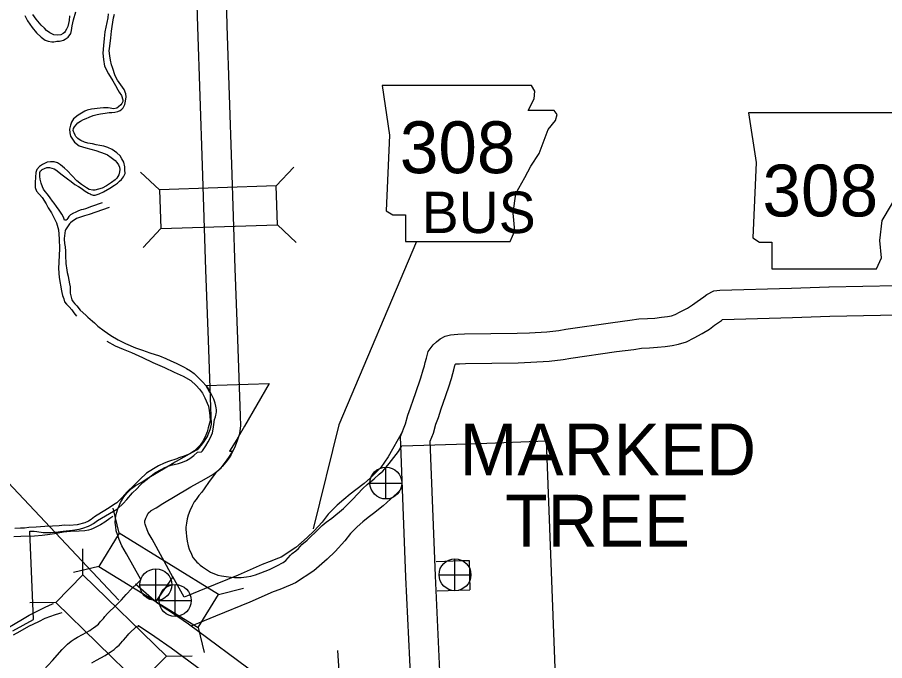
# Model space of a CAD drawing. Extents: x -117616 to 64730, y 54117 to 789866.
# Drawn here: x 61631.6 to 61720, y 55976 to 56041.5 of the extents above; entities that cross this region are included whole.
import ezdxf

# ---------------------------------------------------------------- set-up
doc = ezdxf.new("R2010")
doc.units = 0
for name, color, linetype in [('Level 10', 7, 'Continuous'), ('Level 15', 7, 'Continuous'), ('Level 20', 7, 'Continuous'), ('Level 21', 7, 'Continuous'), ('Level 22', 7, 'Continuous'), ('Level 26', 7, 'Continuous'), ('Level 6', 7, 'Continuous'), ('Level 9', 7, 'Continuous')]:
    doc.layers.add(name, color=color, linetype=linetype)

msp = doc.modelspace()

# ---------------------------------------------------------------- linework, layer by layer
at = {"layer": 'Level 10'}
for p, q in [((61677.652, 55986.174), (61677.742, 55983.175)), ((61647.471, 55984.484), (61645.699, 55981.966))]:
    msp.add_line(p, q, dxfattribs=at)
for points in [[(61647.41, 55996.047), (61647.821, 55996.291), (61649.176, 55997.023), (61649.898, 55997.454), (61650.109, 55997.602), (61650.157, 55997.644), (61650.334, 55997.885), (61650.49, 55998.068), (61650.598, 55998.2), (61650.735, 55998.405), (61650.987, 55998.804), (61651.076, 55999.01), (61651.273, 55999.512), (61651.351, 55999.761), (61651.392, 56000.055), (61651.366, 56000.828), (61651.102, 56008.617), (61650.824, 56015.808), (61650.473, 56026.444), (61650.008, 56040.58), (61649.878, 56045.135)], [(61648.946, 55993.47), (61649.302, 55993.682), (61650.658, 55994.414), (61651.532, 55994.936), (61651.961, 55995.237), (61652.375, 55995.597), (61652.687, 55996.021), (61652.797, 55996.15), (61653.012, 55996.414), (61653.249, 55996.767), (61653.65, 55997.402), (61653.851, 55997.871), (61654.103, 55998.513), (61654.288, 55999.1), (61654.399, 55999.897), (61654.364, 56000.929), (61654.1, 56008.726), (61653.822, 56015.915), (61653.472, 56026.543), (61653.007, 56040.672), (61652.882, 56045.045)], [(61714.345, 56014.067), (61728.08, 56014.327)], [(61671.813, 55971.825), (61671.216, 55984.46), (61670.674, 55998.81), (61671.16, 56000.094), (61671.409, 56000.982), (61671.69, 56001.744), (61671.981, 56002.609), (61672.194, 56003.189), (61672.729, 56004.796), (61672.983, 56005.603), (61673.102, 56006.012), (61673.19, 56006.357), (61673.303, 56006.79), (61673.487, 56007.48), (61673.792, 56007.868), (61674, 56008.141), (61674.345, 56008.469), (61674.694, 56008.748), (61675.206, 56009.046), (61675.756, 56009.177), (61676.505, 56009.221), (61677.188, 56009.262), (61682.545, 56009.323), (61683.798, 56009.387), (61685.572, 56009.484), (61686.785, 56009.61), (61687.509, 56009.758), (61692.291, 56010.443), (61694.043, 56010.66), (61694.937, 56010.784), (61695.846, 56010.834), (61696.589, 56010.885), (61697.266, 56010.962), (61697.862, 56011.042), (61698.28, 56011.123), (61698.654, 56011.236), (61699.175, 56011.507), (61699.894, 56011.894), (61700.432, 56012.229), (61700.892, 56012.584), (61701.579, 56013.049), (61701.861, 56013.275), (61702.595, 56013.653), (61703.19, 56013.725), (61710.506, 56013.931), (61714.32, 56014.067)], [(61674.849, 55971.134), (61674.214, 55984.588), (61673.695, 55998.316), (61674.013, 55999.156), (61674.265, 56000.057), (61674.519, 56000.746), (61674.811, 56001.613), (61675.025, 56002.197), (61675.583, 56003.872), (61675.855, 56004.734), (61675.996, 56005.221), (61676.095, 56005.607), (61676.204, 56006.027), (61676.228, 56006.114), (61676.243, 56006.134), (61676.317, 56006.205), (61676.682, 56006.227), (61677.294, 56006.263), (61682.639, 56006.324), (61683.956, 56006.392), (61685.809, 56006.492), (61687.241, 56006.642), (61688.021, 56006.801), (61692.688, 56007.469), (61694.433, 56007.685), (61695.226, 56007.795), (61696.031, 56007.84), (61696.861, 56007.897), (61697.635, 56007.984), (61698.349, 56008.081), (61699.001, 56008.207), (61699.79, 56008.446), (61700.578, 56008.855), (61701.4, 56009.298), (61702.145, 56009.762), (61702.651, 56010.152), (61703.36, 56010.632), (61703.486, 56010.732), (61710.601, 56010.933), (61714.426, 56011.069)], [(61714.401, 56011.068), (61728.152, 56011.328)], [(61670.881, 55999.307), (61669.403, 55996.717), (61668.658, 55995.642), (61668.215, 55995.19), (61667.589, 55994.603), (61666.959, 55994.018), (61666.104, 55993.354), (61665.52, 55992.917), (61664.876, 55992.391), (61664.196, 55991.794), (61663.279, 55990.883), (61662.684, 55990.077), (61661.877, 55989.201), (61661.158, 55988.518), (61659.999, 55987.498), (61658.496, 55986.512), (61658.239, 55986.395), (61657.294, 55986.013)], [(61644.188, 55984.233), (61642.753, 55986.852), (61642.266, 55987.66), (61641.998, 55988.318), (61641.851, 55988.724), (61641.705, 55989.197), (61641.641, 55989.592), (61641.587, 55990.056), (61641.658, 55990.764), (61641.852, 55991.449), (61641.995, 55991.74), (61642.138, 55992.075), (61642.473, 55992.67), (61642.761, 55993.025), (61643.249, 55993.517), (61643.669, 55993.826), (61644.234, 55994.12), (61644.858, 55994.526), (61647.597, 55996.158)], [(61647.477, 55984.474), (61645.354, 55988.347), (61644.957, 55989.007), (61644.799, 55989.394), (61644.696, 55989.681), (61644.633, 55989.882), (61644.613, 55990.005), (61644.604, 55990.082), (61644.616, 55990.201), (61644.664, 55990.37), (61644.723, 55990.489), (61644.833, 55990.747), (61644.962, 55990.976), (61644.995, 55991.017), (61645.215, 55991.239), (61645.259, 55991.271), (61645.749, 55991.526), (61646.445, 55991.98), (61649.132, 55993.581)], [(61670.795, 55993.536), (61670.314, 55993.045), (61669.635, 55992.409), (61668.903, 55991.73), (61667.923, 55990.968), (61667.367, 55990.553), (61666.816, 55990.102), (61666.245, 55989.601), (61665.556, 55988.916), (61665.001, 55988.164), (61664.016, 55987.095), (61663.182, 55986.304), (61661.822, 55985.106), (61659.947, 55983.876), (61659.422, 55983.637), (61658.365, 55983.21), (61658.261, 55983.172)], [(61657.485, 55986.09), (61657.294, 55986.013), (61656.575, 55985.754), (61654.135, 55984.682), (61650.687, 55983.272), (61648.949, 55982.553), (61648.623, 55982.419), (61647.471, 55984.484)], [(61674.284, 55986.072), (61676.896, 55986.151)], [(61676.897, 55986.151), (61677.652, 55986.174)], [(61658.61, 55983.309), (61658.365, 55983.21), (61657.687, 55982.966), (61655.307, 55981.92), (61651.828, 55980.498), (61650.094, 55979.78), (61649.568, 55979.564), (61649.329, 55979.479)], [(61674.41, 55983.074), (61677.742, 55983.175)]]:
    msp.add_lwpolyline(points, dxfattribs=at)
at = {"layer": 'Level 15'}
for points in [[(61633.884, 55974.536), (61635.186, 55975.957), (61636.182, 55977.102), (61636.741, 55977.626), (61637.116, 55977.95), (61637.4, 55978.142), (61637.748, 55978.344), (61638.257, 55978.622), (61639.002, 55979.032), (61639.179, 55979.154), (61639.394, 55979.311), (61639.624, 55979.459), (61639.739, 55979.566), (61639.882, 55979.687), (61640.065, 55979.9), (61640.199, 55980.051), (61640.391, 55980.261), (61640.537, 55980.442), (61640.809, 55980.752), (61641.686, 55981.614), (61642.219, 55982.17), (61642.714, 55982.707), (61643.282, 55983.311), (61643.826, 55983.836), (61644.188, 55984.188)], [(61667.248, 55966.409), (61659.949, 55971.71), (61656.025, 55974.518), (61649.047, 55979.666), (61647.318, 55980.868), (61646.593, 55981.352), (61646.235, 55981.563), (61645.835, 55981.85), (61643.674, 55983.76)], [(61639.219, 55975.729), (61639.7, 55975.992), (61640.576, 55976.475), (61640.912, 55976.705), (61641.092, 55976.836), (61641.473, 55977.081), (61641.732, 55977.322), (61642.001, 55977.55), (61642.327, 55977.929), (61642.428, 55978.043), (61642.666, 55978.304), (61642.833, 55978.51), (61642.991, 55978.69), (61643.797, 55979.482)], [(61663.181, 55965.668), (61658.196, 55969.275), (61654.261, 55972.092), (61647.3, 55977.227), (61645.629, 55978.388), (61644.996, 55978.811), (61644.595, 55979.048), (61643.963, 55979.5), (61643.946, 55979.516), (61643.853, 55979.421)]]:
    msp.add_lwpolyline(points, dxfattribs=at)
at = {"layer": 'Level 20'}
for p, q in [((61646.113, 56023.953), (61644.186, 56025.757)), ((61657.987, 56024.344), (61659.791, 56026.271)), ((61646.243, 56019.995), (61644.439, 56018.068)), ((61658.117, 56020.386), (61660.044, 56018.582)), ((61641.982, 55988.937), (61641.369, 55991.505)), ((61638.309, 55984.719), (61638.278, 55987.359)), ((61639.908, 55985.563), (61637.34, 55984.951)), ((61652.103, 55982.717), (61654.671, 55983.33)), ((61635.542, 55981.886), (61632.902, 55981.855)), ((61650.029, 55979.343), (61650.642, 55976.775)), ((61646.807, 55976.418), (61649.447, 55976.449)), ((61664.446, 55974.371), (61664.268, 55977.005))]:
    msp.add_line(p, q, dxfattribs=at)
for points in [[(61646.243, 56019.995), (61658.117, 56020.386), (61657.987, 56024.344), (61646.113, 56023.953)], [(61652.103, 55982.717), (61641.982, 55988.937), (61639.908, 55985.563), (61650.029, 55979.343)], [(61646.807, 55976.418), (61638.309, 55984.719), (61635.542, 55981.886), (61644.04, 55973.585)]]:
    msp.add_lwpolyline(points, close=True, dxfattribs=at)
at = {"layer": 'Level 21'}
msp.add_line((61684.02, 56034.585), (61684.02, 56034.585), dxfattribs=at)
msp.add_line((61684.02, 56034.585), (61684.02, 56034.585), dxfattribs=at)
for points in [[(61668.794, 56034.585), (61669.555, 56029.51), (61669.217, 56021.812), (61669.894, 56021.389), (61671.163, 56021.389), (61671.163, 56018.682), (61681.821, 56018.682), (61682.328, 56019.782), (61682.159, 56021.558), (61682.413, 56023.588), (61683.343, 56025.196), (61683.935, 56026.38), (61684.781, 56027.649), (61685.289, 56029.002), (61685.712, 56030.102), (61686.473, 56031.032), (61686.642, 56031.624), (61686.304, 56032.047), (61683.682, 56032.047), (61684.274, 56033.232), (61684.358, 56033.993), (61684.008, 56034.578)], [(61706.131, 56031.814), (61706.893, 56026.738), (61706.554, 56019.041), (61707.231, 56018.618), (61708.5, 56018.618), (61708.5, 56015.911), (61719.158, 56015.911), (61719.666, 56017.011), (61719.497, 56018.787), (61719.75, 56020.817), (61720.681, 56022.424), (61721.273, 56023.609), (61722.119, 56024.877), (61722.626, 56026.231), (61723.049, 56027.331), (61723.811, 56028.261), (61723.98, 56028.853), (61723.641, 56029.276), (61721.019, 56029.276), (61721.611, 56030.46), (61721.696, 56031.222), (61721.345, 56031.806)]]:
    msp.add_lwpolyline(points, close=True, dxfattribs=at)
msp.add_lwpolyline([(61672.279, 56018.696), (61664.377, 56000.005), (61661.751, 55989.382)], dxfattribs=at)
at = {"layer": 'Level 22'}
msp.add_line((61622.881, 56002.408), (61641.974, 55982.109), dxfattribs=at)
at = {"layer": 'Level 26'}
for p, q in [((61669.175, 55992.436), (61669.175, 55995.686)), ((61667.55, 55994.061), (61670.8, 55994.061)), ((61676.216, 55983.087), (61676.216, 55986.337)), ((61645.737, 55982.075), (61645.737, 55985.325)), ((61674.591, 55984.712), (61677.841, 55984.712)), ((61644.112, 55983.7), (61647.362, 55983.7)), ((61647.697, 55980.464), (61647.697, 55983.714)), ((61646.072, 55982.089), (61649.322, 55982.089))]:
    msp.add_line(p, q, dxfattribs=at)
for centre in [(61669.175, 55994.061), (61676.216, 55984.712), (61645.737, 55983.7), (61647.697, 55982.089)]:
    msp.add_circle(centre, 1.625, dxfattribs=at)
at = {"layer": 'Level 6'}
for points in [[(61651.654, 56000.038), (61651.707, 56000.532), (61651.807, 56000.797), (61651.854, 56000.973), (61651.886, 56001.114), (61651.925, 56001.32), (61651.917, 56001.519), (61651.895, 56001.744), (61651.862, 56001.913), (61651.783, 56002.197), (61651.625, 56002.603), (61651.425, 56003.015), (61651.201, 56003.48), (61650.983, 56003.833), (61650.865, 56004.021), (61657.292, 56004.194), (61654.753, 55999.875), (61653.982, 55998.514), (61653.223, 55997.303), (61653.578, 55997.312), (61653.407, 55996.978), (61653.196, 55996.648), (61652.984, 55996.348), (61652.69, 55995.984), (61652.484, 55995.748), (61652.172, 55995.436), (61651.807, 55995.06), (61651.171, 55994.212), (61650.654, 55993.483), (61650.418, 55993.142), (61650.124, 55992.806), (61649.83, 55992.383), (61649.653, 55992.135), (61649.442, 55991.741), (61649.212, 55991.235), (61649.036, 55990.782), (61648.924, 55990.417), (61648.841, 55989.988), (61648.794, 55989.558), (61648.783, 55989.317), (61648.806, 55989.005), (61648.853, 55988.617), (61648.924, 55988.152), (61649.024, 55987.646), (61649.124, 55987.322), (61649.353, 55986.799), (61649.518, 55986.487), (61649.742, 55986.192), (61649.901, 55986.01), (61650.03, 55985.881), (61650.248, 55985.698), (61650.501, 55985.516), (61650.995, 55985.192), (61651.307, 55984.986), (61651.548, 55984.869), (61651.795, 55984.757), (61652.042, 55984.68), (61652.425, 55984.586), (61652.901, 55984.521), (61653.407, 55984.463), (61653.737, 55984.439), (61654.143, 55984.433), (61654.431, 55984.445), (61654.684, 55984.468), (61654.967, 55984.51), (61655.396, 55984.58), (61655.885, 55984.704), (61656.426, 55984.916), (61657.314, 55985.251), (61658.056, 55985.616), (61658.697, 55985.975), (61658.968, 55986.181), (61659.233, 55986.44), (61659.462, 55986.716), (61659.639, 55986.887), (61660.009, 55987.157), (61660.28, 55987.405), (61660.61, 55987.781), (61661.139, 55988.228), (61662.357, 55989.405), (61662.687, 55989.717), (61663.104, 55990.07), (61663.669, 55990.494), (61664.864, 55991.465), (61665.78, 55992.377), (61666.83, 55993.498), (61667.262, 55993.899), (61667.97, 55994.499), (61668.501, 55994.954), (61668.848, 55995.269), (61669.194, 55995.693), (61669.494, 55996.039), (61669.749, 55996.363), (61670.442, 55997.294), (61670.796, 55997.841), (61678.612, 55998.098), (61685.499, 55998.376)], [(61631.159, 55978.995), (61632.198, 55979.59), (61633.28, 55980.148), (61632.882, 55989.16), (61633.333, 55989.142), (61633.618, 55989.119), (61634.249, 55989.027), (61634.603, 55989.018), (61634.847, 55989.022), (61635.073, 55989.036), (61635.51, 55989.068), (61636.279, 55989.17), (61637.232, 55989.271), (61637.927, 55989.349), (61638.281, 55989.45), (61638.857, 55989.658), (61639.091, 55989.768), (61639.377, 55989.952), (61639.796, 55990.233), (61641.835, 55991.448), (61642.396, 55991.973), (61642.76, 55992.392), (61643.363, 55993.068), (61643.8, 55993.487), (61644.141, 55993.832), (61644.399, 55994.104), (61644.854, 55994.468), (61645.126, 55994.707), (61645.701, 55995.14), (61646.272, 55995.453), (61646.636, 55995.632), (61646.976, 55995.775), (61647.308, 55995.89), (61648.044, 55996.06), (61648.357, 55996.152), (61648.606, 55996.249), (61648.85, 55996.364), (61649.181, 55996.557), (61649.614, 55996.857), (61649.982, 55997.218), (61650.398, 55997.229), (61650.495, 55997.349), (61650.824, 55997.855), (61651.077, 55998.272), (61651.272, 55998.643), (61651.407, 55998.937), (61651.501, 55999.185), (61651.583, 55999.555), (61651.654, 56000.038)], [(61685.499, 55998.376), (61686.516, 55971.664)]]:
    msp.add_lwpolyline(points, dxfattribs=at)
at = {"layer": 'Level 9'}
for points in [[(61632.372, 56041.734), (61632.656, 56041.174), (61633.135, 56040.501), (61633.579, 56039.958), (61634.037, 56039.526), (61634.47, 56039.223), (61634.745, 56039.105), (61635.127, 56039.051), (61635.337, 56039.04), (61635.505, 56039.087), (61635.654, 56039.114), (61635.913, 56039.115), (61636.082, 56039.143), (61636.318, 56039.223), (61636.494, 56039.311), (61636.805, 56039.516), (61637.078, 56039.889), (61637.145, 56040.183), (61637.204, 56040.658), (61637.326, 56041.276), (61637.569, 56042.1)], [(61636.938, 56041.701), (61636.899, 56041.217), (61636.844, 56040.893), (61636.757, 56040.588), (61636.629, 56040.322), (61636.499, 56040.105), (61636.414, 56039.991), (61636.279, 56039.874), (61636.035, 56039.763), (61635.737, 56039.72), (61635.325, 56039.763), (61634.928, 56039.946), (61634.597, 56040.193), (61634.388, 56040.415), (61634.063, 56040.753), (61633.548, 56041.333), (61633.187, 56041.809)], [(61640.885, 56041.882), (61640.832, 56041.498), (61640.547, 56040.04), (61640.456, 56039.383), (61640.408, 56038.667), (61640.342, 56037.891), (61640.392, 56037.22), (61640.49, 56036.572), (61640.915, 56035.787), (61641.336, 56035.062), (61641.607, 56034.581), (61641.856, 56034.14), (61642.007, 56033.905), (61642.222, 56033.553), (61642.37, 56033.138), (61642.359, 56032.946), (61642.277, 56032.762), (61642.164, 56032.607), (61641.933, 56032.406), (61641.768, 56032.288), (61641.452, 56032.224), (61640.879, 56032.3), (61640.41, 56032.299), (61640.051, 56032.274), (61639.166, 56032.185), (61638.731, 56032.086), (61638.486, 56031.975), (61637.825, 56031.574), (61637.353, 56031.182), (61637.148, 56030.842), (61637.031, 56030.546), (61636.95, 56030.12), (61636.966, 56029.769), (61637.042, 56029.411)], [(61641.855, 56031.92), (61642.099, 56032.031), (61642.282, 56032.19), (61642.396, 56032.315), (61642.562, 56032.644), (61642.656, 56033), (61642.697, 56033.423), (61642.673, 56033.744), (61642.493, 56034.188), (61641.842, 56035.134), (61641.593, 56035.585), (61641.305, 56036.436), (61641.214, 56036.704), (61641.103, 56037.181), (61641.034, 56037.6), (61640.991, 56038.12), (61641.05, 56038.605), (61641.142, 56039.453), (61641.203, 56040.108), (61641.281, 56040.604), (61641.352, 56041.029), (61641.422, 56041.474), (61641.505, 56041.859)], [(61640.278, 56022.631), (61639.186, 56022.242), (61638.577, 56022.025), (61638.32, 56021.953), (61638.112, 56021.904), (61637.846, 56021.822), (61637.495, 56021.646), (61637.339, 56021.559), (61637.046, 56021.406), (61636.863, 56021.247), (61636.751, 56021.062), (61636.668, 56020.917), (61636.59, 56020.874), (61636.521, 56020.851), (61636.44, 56020.867), (61636.386, 56020.975), (61636.318, 56021.153), (61636.144, 56021.477), (61635.877, 56021.867), (61635.611, 56022.238), (61635.366, 56022.578), (61635.206, 56022.803), (61634.952, 56023.133), (61634.686, 56023.503), (61634.464, 56023.775), (61634.283, 56024.028), (61634.183, 56024.255), (61634.037, 56024.62), (61633.929, 56025.037), (61633.897, 56025.307), (61633.907, 56025.539), (61633.928, 56025.73), (61633.981, 56025.893), (61634.078, 56025.968), (61634.165, 56026.022), (61634.4, 56026.132), (61634.626, 56026.213), (61634.886, 56026.214), (61635.361, 56026.084), (61635.545, 56025.991), (61635.689, 56025.897), (61636.042, 56025.591), (61636.455, 56025.287), (61636.733, 56025.089), (61637.106, 56024.793), (61637.469, 56024.488), (61637.837, 56024.303), (61638.135, 56024.115), (61638.537, 56023.831), (61638.886, 56023.615), (61639.039, 56023.531), (61639.142, 56023.476), (61639.335, 56023.404), (61639.554, 56023.413), (61639.968, 56023.532), (61640.388, 56023.761), (61641.041, 56024.11), (61641.517, 56024.412), (61641.828, 56024.617), (61642.028, 56024.826), (61642.24, 56025.006), (61642.448, 56025.276), (61642.593, 56025.604), (61642.576, 56025.995), (61642.563, 56026.296), (61642.462, 56026.774), (61642.276, 56027.127), (61642.104, 56027.401), (61641.76, 56027.738), (61641.266, 56028.058), (61640.828, 56028.26), (61640.422, 56028.403), (61640.03, 56028.456), (61639.637, 56028.529), (61639.284, 56028.624), (61638.79, 56028.724), (61638.446, 56028.809), (61638.1, 56028.965), (61637.906, 56029.067), (61637.77, 56029.192), (61637.592, 56029.395), (61637.516, 56029.522), (61637.406, 56029.748), (61637.339, 56029.906), (61637.324, 56030.016), (61637.337, 56030.187), (61637.439, 56030.362), (61637.619, 56030.591), (61637.8, 56030.77), (61638.062, 56030.962), (61638.364, 56031.136), (61638.63, 56031.218), (61638.953, 56031.362), (61639.355, 56031.52), (61639.761, 56031.618), (61640.097, 56031.683), (61640.574, 56031.754), (61640.99, 56031.822), (61641.259, 56031.834), (61641.538, 56031.856), (61641.855, 56031.92)], [(61637.042, 56029.411), (61637.224, 56029.118), (61637.457, 56028.826), (61637.923, 56028.445), (61638.582, 56028.222), (61639.603, 56027.945), (61640.576, 56027.626), (61640.791, 56027.515), (61641.192, 56027.261), (61641.576, 56026.936), (61641.764, 56026.743), (61641.934, 56026.51), (61642.034, 56026.273), (61642.075, 56026.024), (61642.027, 56025.77), (61641.949, 56025.496), (61641.765, 56025.136), (61641.593, 56024.968), (61641.224, 56024.711), (61640.914, 56024.497), (61640.691, 56024.356), (61640.271, 56024.137), (61639.877, 56024.02), (61639.501, 56023.923), (61639.312, 56023.905), (61638.949, 56023.99), (61638.672, 56024.148), (61638.169, 56024.478), (61637.682, 56024.859), (61637.158, 56025.418), (61636.718, 56025.881), (61636.416, 56026.16), (61636.032, 56026.485), (61635.714, 56026.692), (61635.388, 56026.818), (61634.999, 56026.821), (61634.662, 56026.757), (61634.182, 56026.535), (61633.872, 56026.32), (61633.616, 56026.018), (61633.509, 56025.732), (61633.461, 56025.228), (61633.424, 56024.714), (61633.427, 56024.192), (61633.574, 56023.806), (61634.151, 56023.169), (61634.54, 56022.512), (61634.768, 56022.101), (61635.09, 56021.592), (61635.471, 56020.875), (61635.593, 56020.6), (61635.825, 56019.866), (61635.886, 56018.955), (61635.901, 56017.941), (61635.81, 56015.928), (61635.89, 56015.028), (61636.109, 56013.671), (61636.148, 56013.472), (61636.221, 56013.174), (61636.346, 56012.828), (61636.439, 56012.55), (61636.62, 56012.287), (61636.892, 56012.018), (61637.165, 56011.708), (61637.388, 56011.416), (61637.645, 56011.057)], [(61640.978, 56022.149), (61638.942, 56021.438), (61638.469, 56021.287), (61637.632, 56021.03), (61637.409, 56020.869), (61637.245, 56020.752), (61637.041, 56020.602), (61636.937, 56020.477), (61636.872, 56020.374), (61636.534, 56019.887), (61636.497, 56019.805), (61636.404, 56018.987), (61636.39, 56018.836), (61636.412, 56018.576), (61636.426, 56018.486), (61636.501, 56018.148), (61636.531, 56017.687), (61636.54, 56017.266), (61636.566, 56016.453), (61636.647, 56015.754), (61636.687, 56015.514), (61636.783, 56015.157), (61636.843, 56014.928), (61636.909, 56014.57), (61636.949, 56014.33), (61636.962, 56014.261), (61636.992, 56014.031), (61637.014, 56013.761), (61637.019, 56013.419), (61637.179, 56012.743), (61637.318, 56012.528), (61637.467, 56012.334), (61637.676, 56012.122), (61638.034, 56011.696), (61638.587, 56011.167), (61638.806, 56010.956), (61639.263, 56010.574), (61639.47, 56010.392), (61639.835, 56010.046), (61640.465, 56009.581), (61641.135, 56009.108), (61641.885, 56008.648), (61642.639, 56008.3), (61643.668, 56007.842), (61644.368, 56007.591), (61645.109, 56007.322), (61646.091, 56007.023), (61646.752, 56006.77), (61647.272, 56006.532), (61647.792, 56006.283), (61648.609, 56005.877), (61648.865, 56005.737), (61649.255, 56005.503), (61649.627, 56005.218), (61649.918, 56004.969), (61650.231, 56004.651), (61650.525, 56004.333), (61650.819, 56004.004), (61651.012, 56003.711), (61651.209, 56003.328), (61651.234, 56003.276)], [(61640.733, 56008.508), (61641.571, 56008.052), (61642.405, 56007.717), (61643.25, 56007.362), (61644.361, 56006.848), (61645.442, 56006.352), (61646.624, 56005.831), (61647.602, 56005.381), (61648.52, 56004.959), (61649.299, 56004.501), (61649.831, 56003.991), (61650.186, 56003.635), (61650.494, 56003.226), (61650.714, 56002.764), (61651.093, 56001.886), (61651.182, 56001.458), (61651.236, 56000.908), (61651.258, 56000.407), (61651.07, 55999.686), (61650.948, 55999.279), (61650.833, 55998.952), (61650.559, 55998.368), (61650.259, 55997.923), (61649.656, 55997.334), (61649.19, 55997.033), (61648.631, 55996.808), (61648.089, 55996.623), (61647.864, 55996.533), (61647.017, 55996.245), (61646.575, 55996.096), (61646.017, 55995.83), (61645.501, 55995.517)], [(61645.501, 55995.517), (61644.793, 55995.054), (61644.102, 55994.421), (61643.528, 55993.844), (61642.79, 55993.139), (61642.305, 55992.586), (61641.759, 55992.06), (61641.419, 55991.834), (61640.983, 55991.534), (61639.748, 55990.777), (61639.486, 55990.605), (61639.128, 55990.358), (61638.875, 55990.187), (61638.494, 55990), (61637.714, 55989.795), (61636.938, 55989.741), (61636.427, 55989.759), (61635.88, 55989.715), (61635.203, 55989.676), (61634.415, 55989.632), (61633.539, 55989.564), (61632.782, 55989.521), (61632.345, 55989.472), (61631.957, 55989.445), (61631.348, 55989.438)], [(61641.352, 55990.664), (61641.052, 55990.432), (61640.519, 55990.067), (61640.1, 55989.818), (61639.68, 55989.599)], [(61639.68, 55989.599), (61639.348, 55989.434), (61639.103, 55989.333), (61638.856, 55989.262), (61638.5, 55989.196), (61637.923, 55989.141), (61637.044, 55989.133), (61636.329, 55989.042), (61635.397, 55988.881), (61634.702, 55988.79), (61634.157, 55988.706), (61633.37, 55988.642), (61631.974, 55988.612), (61631.276, 55988.581)], [(61629.62, 55978.817), (61630.482, 55979.206), (61631.397, 55979.748), (61632.137, 55980.171), (61632.838, 55980.583), (61633.639, 55980.99), (61634.44, 55981.396), (61635.193, 55981.75), (61635.298, 55981.791)], [(61631.216, 55978.598), (61631.921, 55978.967), (61632.797, 55979.477), (61633.815, 55979.943), (61634.47, 55980.273), (61635.038, 55980.508), (61635.393, 55980.614), (61635.935, 55980.798), (61636.185, 55980.867)]]:
    msp.add_lwpolyline(points, dxfattribs=at)

# ---------------------------------------------------------------- texts
at = {"layer": 'Level 21'}
for s, height, p in [('308', 5.28, (61670.594, 56025.649)), ('308', 5.28, (61707.548, 56021.24)), ('BUS', 4.224, (61672.823, 56019.542))]:
    msp.add_text(s, height=height, dxfattribs=at).set_placement(p)
at = {"layer": 'Level 6'}
for s, p in [('MARKED', (61676.69, 55994.845)), ('TREE', (61681.337, 55987.59))]:
    msp.add_text(s, height=5.28, dxfattribs=at).set_placement(p)

doc.saveas('drawing.dxf')
